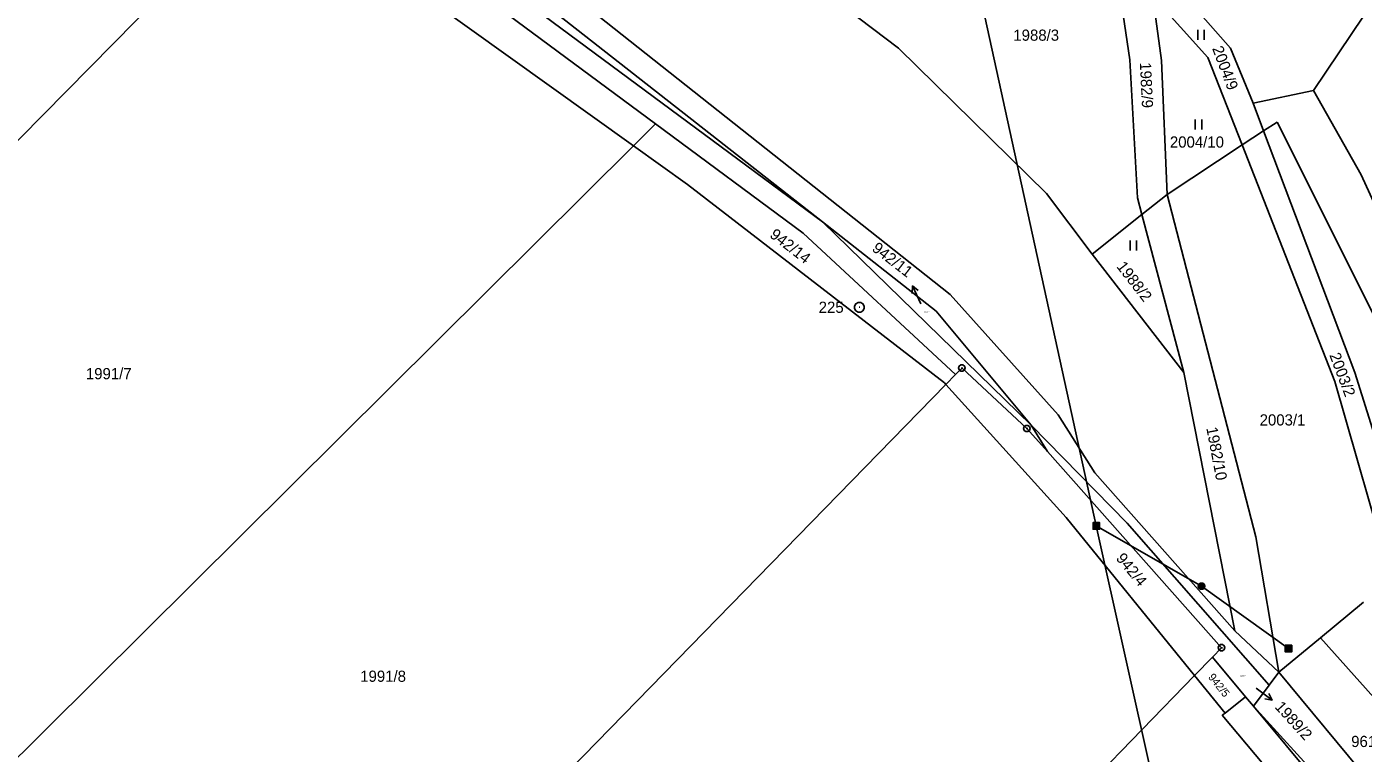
# Model space of a CAD drawing. Extents: x -609861 to -605046, y -1120287 to -1116307.
# Drawn here: x -608045.2 to -607842.1, y -1118658.5 to -1118548.1 of the extents above; entities that cross this region are included whole.
import ezdxf

# ---------------------------------------------------------------- set-up
doc = ezdxf.new("R2010")
doc.units = 0
for name, color, linetype in [('Vrstva 1', 7, 'Continuous'), ('Vrstva 2', 7, 'Continuous'), ('Vrstva 3', 7, 'Continuous'), ('Vrstva 6', 7, 'Continuous'), ('Vrstva 7', 7, 'Continuous'), ('Vrstva 8', 7, 'Continuous')]:
    doc.layers.add(name, color=color, linetype=linetype)

msp = doc.modelspace()

# ---------------------------------------------------------------- linework, layer by layer
at = {"layer": 'Vrstva 1'}
for p, q in [((-608110.26, -1118629.98), (-608007.13, -1118525.41)), ((-607849.63, -1118557.8), (-607828.91, -1118527.06)), ((-607904.83, -1118588.81), (-607974.48, -1118533.66)), ((-607924.25, -1118577.78), (-607977.01, -1118536.43)), ((-607877.52, -1118553.13), (-607879.92, -1118536.98)), ((-607862.24, -1118551.38), (-607874.91, -1118536.86)), ((-607974.5, -1118540.57), (-607924.25, -1118577.78)), ((-607984.48, -1118543.61), (-607952.96, -1118566.23)), ((-607949.65, -1118562.85), (-607976.77, -1118542.79)), ((-607874.02, -1118543.52), (-607865.67, -1118552.77)), ((-607874.02, -1118543.52), (-607872.72, -1118553.23)), ((-607912.71, -1118551.36), (-607920.61, -1118545.38)), ((-607890.19, -1118573.46), (-607912.71, -1118551.36)), ((-607858.8, -1118559.72), (-607862.24, -1118551.38)), ((-607876.38, -1118574.14), (-607877.52, -1118553.13)), ((-607872.72, -1118553.23), (-607871.87, -1118573.59)), ((-607865.67, -1118552.77), (-607860.45, -1118566.09)), ((-607858.8, -1118559.72), (-607849.63, -1118557.8)), ((-607849.63, -1118557.8), (-607842.36, -1118570.61)), ((-607857.2, -1118563.96), (-607858.8, -1118559.72)), ((-607949.65, -1118562.85), (-607952.96, -1118566.23)), ((-607927.18, -1118579.47), (-607949.65, -1118562.85)), ((-607860.45, -1118566.09), (-607857.2, -1118563.96)), ((-607857.2, -1118563.96), (-607855.15, -1118562.61)), ((-607843.35, -1118600.65), (-607857.2, -1118563.96)), ((-607855.15, -1118562.61), (-607825.61, -1118621.63)), ((-607952.96, -1118566.23), (-608070.31, -1118682.67)), ((-607952.96, -1118566.23), (-607944.76, -1118572.11)), ((-607871.87, -1118573.59), (-607860.45, -1118566.09)), ((-607860.45, -1118566.09), (-607846.35, -1118602.04)), ((-607944.76, -1118572.11), (-607905.72, -1118602.25)), ((-607842.36, -1118570.61), (-607835.61, -1118585.51)), ((-607883.24, -1118582.7), (-607890.19, -1118573.46)), ((-607875.71, -1118576.66), (-607876.38, -1118574.14)), ((-607871.87, -1118573.59), (-607875.71, -1118576.66)), ((-607871.87, -1118573.59), (-607858.4, -1118625.63)), ((-607924.25, -1118577.78), (-607892.53, -1118608.68)), ((-607906.96, -1118591.34), (-607924.25, -1118577.78)), ((-607875.71, -1118576.66), (-607883.24, -1118582.7)), ((-607869.3, -1118600.67), (-607875.71, -1118576.66)), ((-607904.01, -1118600.98), (-607927.18, -1118579.47)), ((-607869.3, -1118600.67), (-607883.24, -1118582.7)), ((-607888.41, -1118607.12), (-607904.83, -1118588.81)), ((-607892.53, -1118608.68), (-607906.96, -1118591.34)), ((-607904.01, -1118600.98), (-607903.04, -1118599.99)), ((-607903.04, -1118599.99), (-607893.17, -1118609.18)), ((-607861.59, -1118639.94), (-607869.3, -1118600.67)), ((-607834.28, -1118629.6), (-607843.35, -1118600.65)), ((-608032.52, -1118732.51), (-607905.49, -1118602.5)), ((-607905.72, -1118602.25), (-607905.49, -1118602.5)), ((-607905.49, -1118602.5), (-607904.01, -1118600.98)), ((-607905.49, -1118602.5), (-607887.22, -1118622.69)), ((-607846.35, -1118602.04), (-607837.73, -1118632.23)), ((-607892.53, -1118608.68), (-607877.92, -1118623.58)), ((-607890.07, -1118612.67), (-607892.53, -1118608.68)), ((-607882.85, -1118615.93), (-607888.41, -1118607.12)), ((-607893.17, -1118609.18), (-607890.07, -1118612.67)), ((-607863.58, -1118642.48), (-607890.07, -1118612.67)), ((-607861.59, -1118639.94), (-607882.85, -1118615.93)), ((-607887.22, -1118622.69), (-607867.69, -1118646.71)), ((-607877.92, -1118623.58), (-607856.36, -1118648.18)), ((-607858.4, -1118625.63), (-607854.9, -1118646.2)), ((-607848.57, -1118640.98), (-607842.02, -1118635.59)), ((-607854.9, -1118646.2), (-607861.59, -1118639.94)), ((-607854.9, -1118646.2), (-607848.57, -1118640.98)), ((-607823.39, -1118669.18), (-607848.57, -1118640.98)), ((-607864.99, -1118643.93), (-607863.58, -1118642.48)), ((-607867.69, -1118646.71), (-607864.99, -1118643.93)), ((-607859.93, -1118649.95), (-607864.99, -1118643.93)), ((-607996.81, -1118779.61), (-607867.69, -1118646.71)), ((-607867.69, -1118646.71), (-607863.05, -1118652.42)), ((-607856.36, -1118648.18), (-607854.9, -1118646.2)), ((-607854.9, -1118646.2), (-607834.42, -1118670.86)), ((-607858.72, -1118651.39), (-607856.36, -1118648.18)), ((-607859.93, -1118649.95), (-607863.05, -1118652.42)), ((-607858.72, -1118651.39), (-607859.93, -1118649.95)), ((-607826.21, -1118687.09), (-607858.72, -1118651.39)), ((-607829.4, -1118686.53), (-607858.72, -1118651.39)), ((-607863.05, -1118652.42), (-607863.48, -1118652.76)), ((-607863.48, -1118652.76), (-607832.58, -1118689.51))]:
    msp.add_line(p, q, dxfattribs=at)
at = {"layer": 'Vrstva 3'}
for p, q in [((-607867.22, -1118548.59), (-607867.22, -1118550.09)), ((-607866.22, -1118550.09), (-607866.22, -1118548.59)), ((-607867.6, -1118562.22), (-607867.6, -1118563.72)), ((-607866.6, -1118563.72), (-607866.6, -1118562.22)), ((-607877.5, -1118580.6), (-607877.5, -1118582.1)), ((-607876.5, -1118582.1), (-607876.5, -1118580.6))]:
    msp.add_line(p, q, dxfattribs=at)
at = {"layer": 'Vrstva 6'}
for p, q in [((-607902.89, -1118531.42), (-607882.63, -1118623.98)), ((-607882.63, -1118623.98), (-607866.62, -1118633.14)), ((-607882.63, -1118623.98), (-607869, -1118685.16)), ((-607866.62, -1118633.14), (-607853.42, -1118642.62))]:
    msp.add_line(p, q, dxfattribs=at)
for points in [[(-607883.13, -1118623.48), (-607882.13, -1118623.48), (-607882.13, -1118624.48), (-607883.13, -1118624.48), (-607883.13, -1118623.48), (-607883.07, -1118623.54), (-607882.19, -1118623.54), (-607882.19, -1118623.62), (-607883.07, -1118623.62), (-607883.07, -1118623.7), (-607882.19, -1118623.7), (-607882.19, -1118623.78), (-607883.07, -1118623.78), (-607883.07, -1118623.86), (-607882.19, -1118623.86), (-607882.19, -1118623.94), (-607883.07, -1118623.94), (-607883.07, -1118624.02), (-607882.19, -1118624.02), (-607882.19, -1118624.1), (-607883.07, -1118624.1), (-607883.07, -1118624.18), (-607882.19, -1118624.18), (-607882.19, -1118624.26), (-607883.07, -1118624.26), (-607883.07, -1118624.34), (-607882.19, -1118624.34), (-607882.19, -1118624.42), (-607883.07, -1118624.42)], [(-607866.77, -1118632.66), (-607866.46, -1118632.66), (-607866.21, -1118632.84), (-607866.11, -1118633.13), (-607866.21, -1118633.42), (-607866.46, -1118633.6), (-607866.77, -1118633.6), (-607867.02, -1118633.42), (-607867.12, -1118633.13), (-607867.02, -1118632.84), (-607866.77, -1118632.66), (-607866.74, -1118632.7), (-607866.5, -1118632.7), (-607866.34, -1118632.78), (-607866.9, -1118632.78), (-607866.98, -1118632.86), (-607866.26, -1118632.86), (-607866.26, -1118632.94), (-607866.98, -1118632.94), (-607867.02, -1118633.02), (-607866.22, -1118633.02), (-607866.18, -1118633.1), (-607867.06, -1118633.1), (-607867.06, -1118633.18), (-607866.18, -1118633.18), (-607866.21, -1118633.26), (-607867.02, -1118633.26), (-607867.01, -1118633.34), (-607866.2, -1118633.34), (-607866.25, -1118633.42), (-607866.97, -1118633.42), (-607866.89, -1118633.5), (-607866.33, -1118633.5), (-607866.44, -1118633.58), (-607866.78, -1118633.58)], [(-607853.92, -1118642.12), (-607852.92, -1118642.12), (-607852.92, -1118643.12), (-607853.92, -1118643.12), (-607853.92, -1118642.12), (-607853.86, -1118642.18), (-607852.98, -1118642.18), (-607852.98, -1118642.26), (-607853.86, -1118642.26), (-607853.86, -1118642.34), (-607852.98, -1118642.34), (-607852.98, -1118642.42), (-607853.86, -1118642.42), (-607853.86, -1118642.5), (-607852.98, -1118642.5), (-607852.98, -1118642.58), (-607853.86, -1118642.58), (-607853.86, -1118642.66), (-607852.98, -1118642.66), (-607852.98, -1118642.74), (-607853.86, -1118642.74), (-607853.86, -1118642.82), (-607852.98, -1118642.82), (-607852.98, -1118642.9), (-607853.86, -1118642.9), (-607853.86, -1118642.98), (-607852.98, -1118642.98), (-607852.98, -1118643.06), (-607853.86, -1118643.06)]]:
    msp.add_lwpolyline(points, dxfattribs=at)
at = {"layer": 'Vrstva 7'}
for p, q in [((-607910.562, -1118587.518), (-607909.3, -1118590.24)), ((-607855.899, -1118650.435), (-607858.31, -1118648.65))]:
    msp.add_line(p, q, dxfattribs=at)
for points in [[(-607910.595, -1118588.636), (-607910.562, -1118587.518), (-607909.687, -1118588.215)], [(-607856.405, -1118649.438), (-607855.899, -1118650.435), (-607857, -1118650.242)]]:
    msp.add_lwpolyline(points, dxfattribs=at)
at = {"layer": 'Vrstva 8'}
for p, q in [((-607918.68, -1118590.75), (-607918.58, -1118590.75)), ((-607903.16, -1118599.99), (-607902.92, -1118599.99)), ((-607893.29, -1118609.18), (-607893.05, -1118609.18)), ((-607863.7, -1118642.48), (-607863.46, -1118642.48))]:
    msp.add_line(p, q, dxfattribs=at)
for points in [[(-607918.44, -1118590.03), (-607918.1, -1118590.22), (-607917.91, -1118590.56), (-607917.91, -1118590.95), (-607918.1, -1118591.29), (-607918.44, -1118591.48), (-607918.83, -1118591.48), (-607919.17, -1118591.29), (-607919.36, -1118590.95), (-607919.36, -1118590.56), (-607919.17, -1118590.22), (-607918.83, -1118590.03)], [(-607902.89, -1118599.51), (-607902.64, -1118599.69), (-607902.54, -1118599.98), (-607902.64, -1118600.27), (-607902.89, -1118600.45), (-607903.2, -1118600.45), (-607903.45, -1118600.27), (-607903.55, -1118599.98), (-607903.45, -1118599.69), (-607903.2, -1118599.51)], [(-607893.02, -1118608.7), (-607892.77, -1118608.88), (-607892.67, -1118609.17), (-607892.77, -1118609.46), (-607893.02, -1118609.64), (-607893.33, -1118609.64), (-607893.58, -1118609.46), (-607893.68, -1118609.17), (-607893.58, -1118608.88), (-607893.33, -1118608.7)], [(-607863.43, -1118642), (-607863.18, -1118642.18), (-607863.08, -1118642.47), (-607863.18, -1118642.76), (-607863.43, -1118642.94), (-607863.74, -1118642.94), (-607863.99, -1118642.76), (-607864.09, -1118642.47), (-607863.99, -1118642.18), (-607863.74, -1118642)]]:
    msp.add_lwpolyline(points, close=True, dxfattribs=at)

# ---------------------------------------------------------------- texts
at = {"layer": 'Vrstva 2'}
for s, height, p in [('1988/3', 1.7, (-607895.237, -1118550.25)), ('2004/10', 1.7, (-607871.443, -1118566.49)), ('942/11', 0.2, (-607908.772, -1118591.57)), ('1991/7', 1.7, (-608036.207, -1118601.69)), ('2003/1', 1.7, (-607857.803, -1118608.72)), ('1991/8', 1.7, (-607994.507, -1118647.67)), ('1989/2', 0.2, (-607860.804, -1118646.89)), ('961/2', 1.7, (-607843.883, -1118657.58))]:
    msp.add_text(s, height=height, dxfattribs=at).set_placement(p)
for s, height, rotation, p in [('2004/9', 1.7, 290.71879, (-607865.046, -1118551.412)), ('1982/9', 1.7, 272.72791, (-607876.011, -1118553.562)), ('942/14', 1.7, 322.17417, (-607932.392, -1118579.986)), ('1988/2', 1.7, 307.79293, (-607879.639, -1118584.58)), ('2003/2', 1.7, 290.71879, (-607847.226, -1118598.022)), ('1982/10', 1.7, 280.80662, (-607865.916, -1118609.106)), ('942/4', 1.7, 309.62639, (-607879.729, -1118628.953)), ('942/5', 1.2, 308.70966, (-607865.695, -1118646.991))]:
    msp.add_text(s, height=height, rotation=rotation, dxfattribs=at).set_placement(p)
at = {"layer": 'Vrstva 7'}
for s, rotation, p in [('942/11', 322.17417, (-607916.857, -1118582.051)), ('1989/2', 312.31929, (-607855.593, -1118651.555))]:
    msp.add_text(s, height=1.7, rotation=rotation, dxfattribs=at).set_placement(p)
at = {"layer": 'Vrstva 8'}
msp.add_text('225', height=1.7, dxfattribs=at).set_placement((-607924.825, -1118591.6))

doc.saveas('drawing.dxf')
